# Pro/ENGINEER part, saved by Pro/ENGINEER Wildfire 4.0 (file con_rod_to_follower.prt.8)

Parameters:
  METRIC = "NO"

Other parameters: PITCH, DRILL_POINT_ANGLE, DRILL_DEPTH, DRILL_DIAMETER, THREAD_DIAMETER, THREADS_PER_INCH, THREAD_DEPTH, THREAD_LENGTH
